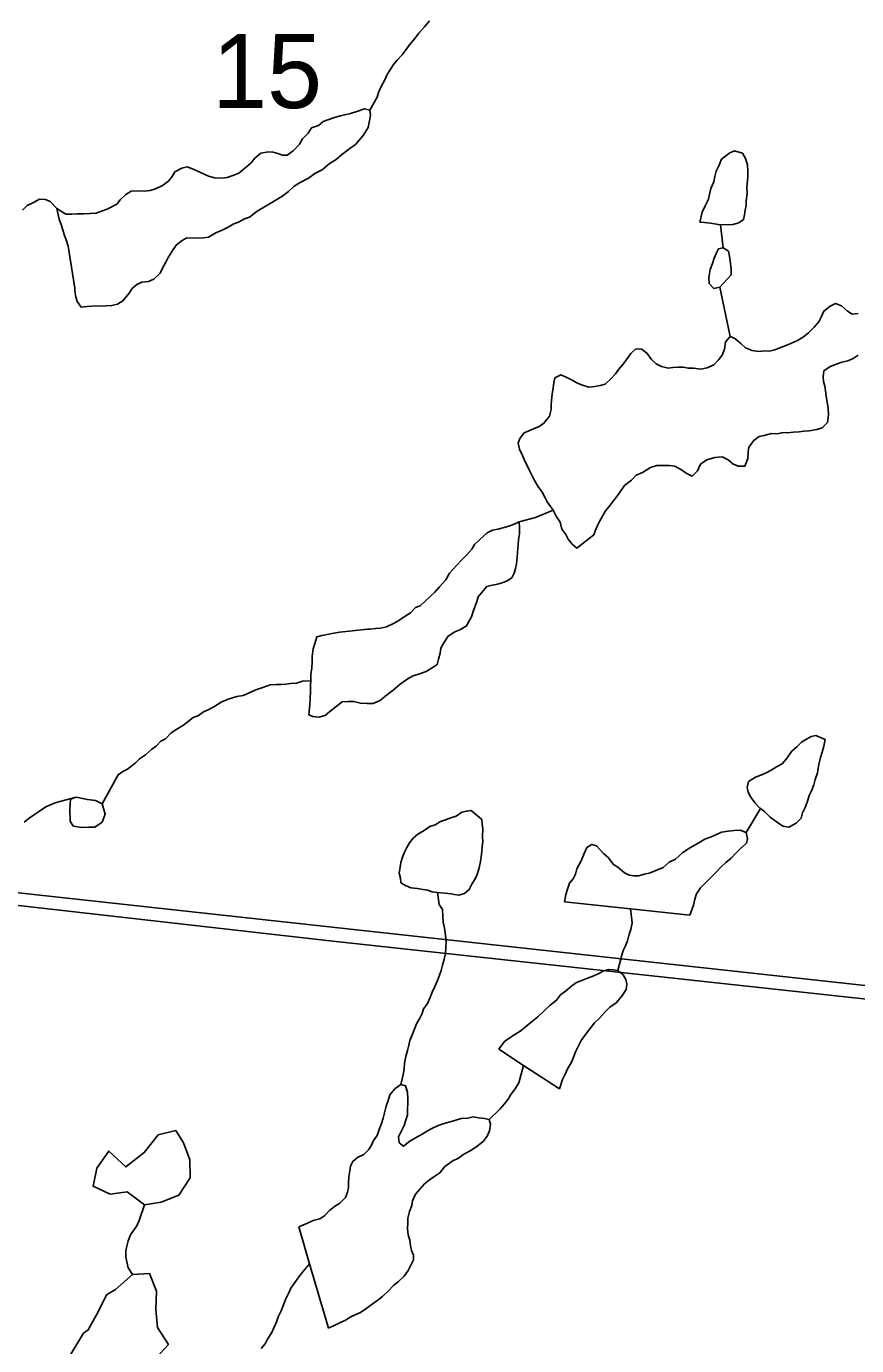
# Model space of a CAD drawing. Extents: x 1310247 to 1664935, y 284496 to 704931.
# Drawn here: x 1503058 to 1505539, y 507787 to 511730 of the extents above; entities that cross this region are included whole.
import ezdxf

# ---------------------------------------------------------------- set-up
doc = ezdxf.new("R2010")
doc.units = 0
for name, color, linetype in [('GM_X_County', 7, 'Continuous'), ('GM_X_County_Subdivision_Text', 7, 'Continuous'), ('GM_X_Minor_River', 7, 'Continuous'), ('GM_X_Minor_River_Text', 7, 'Continuous'), ('GM_X_US_Location', 7, 'Continuous')]:
    doc.layers.add(name, color=color, linetype=linetype)

msp = doc.modelspace()

# ---------------------------------------------------------------- linework, layer by layer
at = {"layer": 'GM_X_County'}
for points in [[(1501457.6, 514459.3), (1506637.6, 513990.6), (1506128.6, 508801.3), (1500914.6, 509372.6)], [(1500914.6, 509372.6), (1506128.6, 508801.3), (1505662.2, 503437.3), (1500316.1, 503893.5)]]:
    msp.add_lwpolyline(points, close=True, dxfattribs=at)
at = {"layer": 'GM_X_County_Subdivision_Text'}
msp.add_lwpolyline([(1502061.4, 509213.1), (1502095.3, 509209.3), (1503964.4, 508997.2), (1506100.4, 508764.4)], dxfattribs=at)
at = {"layer": 'GM_X_Minor_River'}
for points in [[(1503295.9, 510894.9), (1503314, 510896.3), (1503330.2, 510899.8), (1503346.6, 510909.4), (1503365.5, 510932.8), (1503373.9, 510946.6), (1503388.4, 510958.2), (1503402.7, 510965.7), (1503422.9, 510967.1), (1503439.2, 510974.6), (1503457.8, 510992.1), (1503464.4, 511007.9), (1503475, 511025.6), (1503481.5, 511039.4), (1503496.4, 511063), (1503506.9, 511076.7), (1503523.4, 511090.2), (1503537.7, 511097.8), (1503565.8, 511096.9), (1503587.9, 511098.2), (1503602.1, 511099.8), (1503624.6, 511113.1), (1503642.9, 511120.6), (1503661.3, 511130), (1503677.7, 511139.6), (1503692, 511145.1), (1503710.4, 511154.6), (1503724.6, 511160.2), (1503747.3, 511177.5), (1503769.8, 511190.8), (1503786.2, 511200.3), (1503821.1, 511221.3), (1503841.7, 511236.7), (1503858.2, 511252.2), (1503876.7, 511263.6), (1503901.3, 511276.9), (1503919.8, 511290.4), (1503942.3, 511301.7), (1503962.9, 511319.1), (1503983.5, 511332.5), (1504000, 511346), (1504024.7, 511365.3), (1504041.2, 511376.8), (1504064.2, 511404.1), (1504079, 511427.7), (1504083.7, 511447.6), (1504086.3, 511465.5), (1504084.8, 511479.6), (1504068.9, 511484.1), (1504048.5, 511476.7), (1504026.2, 511469.4), (1504010, 511465.9), (1503995.8, 511462.3), (1503975.5, 511456.9), (1503945, 511445.9), (1503930.6, 511434.3), (1503910.2, 511426.9), (1503899.7, 511411.2), (1503883, 511393.7), (1503874.5, 511377.9), (1503855.7, 511358.5), (1503837.2, 511345), (1503823.2, 511345.4), (1503809.2, 511349.9), (1503795.3, 511354.3), (1503781.3, 511354.8), (1503759.1, 511351.4), (1503740.5, 511336), (1503730, 511322.3), (1503715.5, 511310.7), (1503692.8, 511291.4), (1503678.5, 511285.8), (1503658.2, 511278.4), (1503642.1, 511276.9), (1503620, 511277.6), (1503602, 511282.1), (1503574.3, 511295), (1503556.5, 511303.6), (1503538.7, 511310.1), (1503522.5, 511306.6), (1503502, 511295.2), (1503493.5, 511281.5), (1503483, 511267.8), (1503464.5, 511254.3), (1503444.1, 511245), (1503427.8, 511239.5), (1503409.7, 511238), (1503391.6, 511238.6), (1503371.5, 511237.2), (1503355.1, 511227.7), (1503338.5, 511212.1), (1503328, 511198.5), (1503299.4, 511183.3), (1503283.1, 511177.8), (1503266.9, 511172.3), (1503248.7, 511170.8), (1503230.6, 511169.4), (1503208.5, 511170.1), (1503194.4, 511168.5), (1503176.3, 511169.1), (1503148.8, 511186)], [(1505131.9, 511137.4), (1505168.6, 511137.6), (1505186.8, 511143), (1505201.2, 511152.6), (1505203.7, 511166.6), (1505206.1, 511180.5), (1505208.6, 511194.5), (1505209.1, 511208.5), (1505211.8, 511230.4), (1505210.4, 511248.5), (1505213.5, 511280.5), (1505214.1, 511298.5), (1505212.6, 511316.5), (1505207.2, 511334.8), (1505197.7, 511351.1), (1505173.8, 511357.8), (1505159.6, 511352.2), (1505134.8, 511333), (1505128.2, 511315.1), (1505119.6, 511297.4), (1505115, 511281.5), (1505112.5, 511265.6), (1505103.8, 511245.8), (1505099.2, 511227.9), (1505096.7, 511214), (1505086, 511194.2), (1505077.3, 511174.5), (1505070.4, 511144.6)], [(1503148.8, 511186), (1503152.3, 511171.8), (1503155.7, 511153.7), (1503163.2, 511135.4), (1503166.7, 511121.3), (1503172.2, 511105.1), (1503177.7, 511088.9), (1503183.2, 511072.7), (1503202.5, 510948.1)], [(1505070.4, 511144.6), (1505084.4, 511144.2), (1505102.4, 511141.6), (1505120.4, 511139.1), (1505131.9, 511137.4)], [(1505130.2, 510950.5), (1505112, 510947), (1505098.4, 510961.4), (1505097, 510979.5), (1505101.8, 511003.4), (1505108.4, 511021.2), (1505113, 511037.1), (1505119.5, 511051), (1505126, 511064.8), (1505140.1, 511068.3), (1505155.9, 511057.8), (1505159.4, 511043.7), (1505161, 511029.6), (1505164.1, 511003.5), (1505163.6, 510987.5), (1505130.2, 510950.5)], [(1505119.5, 511051), (1505113, 511037.1), (1505108.4, 511021.2), (1505101.8, 511003.4), (1505097, 510979.5), (1505098.4, 510961.4), (1505112, 510947), (1505130.2, 510950.5)], [(1505130.2, 510950.5), (1505163.6, 510987.5), (1505164.1, 511003.5), (1505161, 511029.6), (1505159.4, 511043.7), (1505155.9, 511057.8), (1505140.1, 511068.3), (1505126, 511064.8), (1505119.5, 511051)], [(1503202.5, 510948.1), (1503203, 510941.8), (1503204.5, 510925.8), (1503209.9, 510907.6), (1503221.4, 510891.2), (1503239.6, 510892.6), (1503253.7, 510894.2), (1503295.9, 510894.9)], [(1505543.5, 510871.6), (1505525.4, 510870.1), (1505511.6, 510878.6), (1505494.1, 510895.1), (1505476.2, 510901.7), (1505459.9, 510894.2), (1505441.3, 510878.7), (1505432.7, 510861), (1505426.2, 510847.1), (1505411.6, 510831.6), (1505395, 510814), (1505380.5, 510802.5), (1505362, 510791), (1505335.6, 510779.8), (1505317.2, 510772.4), (1505294.8, 510763), (1505278.6, 510759.5), (1505264.6, 510760), (1505246.4, 510758.5), (1505226.4, 510761.1), (1505206.6, 510769.8), (1505193, 510782.2), (1505175.4, 510796.8), (1505161.5, 510803.2), (1505146.9, 510787.6)], [(1505146.9, 510787.6), (1505144.2, 510765.7), (1505137.6, 510747.9), (1505127.1, 510734.2), (1505112.5, 510718.6), (1505092.1, 510709.2), (1505073.9, 510705.8), (1505051.9, 510708.4), (1505035.8, 510708.9), (1505021.9, 510711.4), (1505005.8, 510711.9), (1504989.7, 510710.4), (1504975.6, 510708.8), (1504955.6, 510713.4), (1504939.8, 510721.9), (1504926.2, 510734.4), (1504912.7, 510752.8), (1504897, 510765.3), (1504879, 510765.9), (1504864.5, 510752.3), (1504854, 510738.6), (1504841.3, 510721), (1504828.8, 510705.3), (1504818.3, 510691.6), (1504805.8, 510678), (1504787.1, 510660.5), (1504772.9, 510657), (1504756.7, 510653.4), (1504738.6, 510652), (1504716.7, 510658.7), (1504702.8, 510665.1), (1504687.1, 510673.6), (1504671.3, 510682.1), (1504655.4, 510688.6), (1504637, 510679.2), (1504634.5, 510665.2), (1504632, 510649.3), (1504629.4, 510631.3), (1504626.8, 510613.4), (1504626.3, 510599.4), (1504625.9, 510585.3), (1504621.2, 510565.5), (1504604.4, 510543.9), (1504590, 510534.4), (1504573.7, 510526.9), (1504559.5, 510521.3), (1504545.2, 510515.7), (1504532.6, 510498.1), (1504528.1, 510484.2), (1504531.5, 510466), (1504540.9, 510447.7), (1504546.5, 510433.5), (1504559.7, 510407.1), (1504567.2, 510390.8), (1504576.6, 510372.5), (1504586.2, 510356.2), (1504599.6, 510337.7), (1504607.2, 510323.5), (1504614.7, 510309.2), (1504632, 510284.6), (1504641.5, 510266.3), (1504652.9, 510247.9), (1504658.3, 510227.7), (1504669.8, 510211.3), (1504677.3, 510197.1), (1504688.9, 510182.7), (1504702.6, 510170.3)], [(1505449.7, 510612.1), (1505443.9, 510654.3), (1505440.4, 510668.4), (1505438.8, 510682.5), (1505441.4, 510700.4), (1505460, 510713.9), (1505476.2, 510719.4), (1505494.5, 510726.8), (1505512.7, 510730.3), (1505529.1, 510737.8), (1505543.4, 510747.3)], [(1504702.6, 510170.3), (1504754.1, 510210.7), (1504758.6, 510224.6), (1504765.1, 510238.4), (1504771.6, 510252.3), (1504788.6, 510281.8), (1504799.1, 510295.5), (1504811.7, 510311.1), (1504822.2, 510324.8), (1504832.7, 510338.5), (1504845.4, 510358.2), (1504866, 510373.6), (1504880.6, 510389.1), (1504898.9, 510396.6), (1504923.5, 510411.9), (1504941.8, 510417.3), (1504980, 510418.1), (1504996, 510415.6), (1505015.8, 510405), (1505029.5, 510394.6), (1505047.3, 510386), (1505063.9, 510401.5), (1505072.6, 510421.3), (1505091.1, 510434.7), (1505115.4, 510442), (1505137.6, 510443.3), (1505155.4, 510434.8), (1505169, 510422.3), (1505184.9, 510415.8), (1505205, 510415.2), (1505213.8, 510439), (1505214.4, 510459), (1505216.9, 510472.9), (1505231.6, 510492.5), (1505248.1, 510504), (1505262.3, 510507.6), (1505284.5, 510512.9), (1505302.6, 510512.4), (1505318.8, 510515.9), (1505332.8, 510515.4), (1505349, 510516.9), (1505367.1, 510518.4), (1505381.2, 510520), (1505397.3, 510521.5), (1505419.6, 510524.8), (1505435.8, 510530.3), (1505452.4, 510545.8), (1505455.2, 510569.8), (1505453.8, 510587.8), (1505452.3, 510601.9), (1505449.7, 510612.1)], [(1503902.5, 509672), (1503914.4, 509667.7), (1503932.4, 509665.1), (1503950.7, 509670.5), (1503965.1, 509682.1), (1503983.7, 509697.6), (1504002.2, 509711), (1504020.4, 509712.5), (1504036.4, 509712), (1504056.4, 509707.3), (1504076.4, 509706.7), (1504094.5, 509706.2), (1504114.9, 509715.6), (1504129.3, 509727.1), (1504154.1, 509746.4), (1504174.8, 509763.8), (1504199.4, 509781.1), (1504213.8, 509788.6), (1504236.1, 509796), (1504252.4, 509801.5), (1504270.8, 509812.9), (1504285.2, 509822.5), (1504289.7, 509838.4), (1504294.4, 509856.3), (1504296.9, 509872.2), (1504305.4, 509888), (1504318.2, 509907.6), (1504338.7, 509921), (1504352.9, 509926.6), (1504373.4, 509938), (1504379.9, 509951.8), (1504388.4, 509965.6), (1504392.9, 509981.5), (1504404, 510011.2), (1504408.4, 510025.1), (1504423.1, 510042.6), (1504433.6, 510056.3), (1504449.8, 510059.8), (1504466, 510063.4), (1504480.1, 510066.9), (1504494.4, 510072.5), (1504508.8, 510082.1), (1504515.3, 510095.9), (1504519.7, 510109.8), (1504522.2, 510123.7), (1504524.9, 510143.7), (1504525.3, 510157.7), (1504528.1, 510181.6), (1504528.6, 510195.7), (1504531.2, 510213.6), (1504531.7, 510229.6), (1504530.4, 510249.7), (1504516.1, 510242.1), (1504499.8, 510236.6), (1504481.6, 510231.2), (1504467.4, 510227.6), (1504451.2, 510224.1), (1504434.9, 510216.6), (1504412, 510195.2), (1504397.5, 510181.7), (1504389, 510167.9), (1504374.4, 510150.3), (1504359.9, 510136.8), (1504343.2, 510119.2), (1504322.4, 510095.8), (1504311.7, 510076.1), (1504292.9, 510054.7), (1504278.3, 510039.1), (1504263.8, 510025.5), (1504249.3, 510011.9), (1504234.8, 509998.4), (1504220.5, 509992.8), (1504205.9, 509977.2), (1504189.5, 509967.7), (1504171, 509954.3), (1504156.7, 509946.7), (1504134.2, 509935.4), (1504116, 509931.9), (1504101.9, 509930.3), (1504085.8, 509928.8), (1504077.8, 509928.4)], [(1504077.8, 509928.4), (1503995.1, 509919.6), (1503976.9, 509916.2), (1503956.7, 509912.8), (1503940.5, 509909.3), (1503926.3, 509905.7), (1503919.6, 509885.9), (1503915, 509870), (1503912.3, 509848), (1503911.8, 509832), (1503911.1, 509812), (1503908.5, 509794.1), (1503907.9, 509774), (1503907.4, 509760), (1503906.8, 509742), (1503906.1, 509720), (1503905.5, 509702), (1503902.5, 509672)], [(1505445.2, 509598.3), (1505417.5, 509611.2), (1505403.3, 509607.7), (1505389, 509600.1), (1505374.6, 509590.5), (1505360.1, 509576.9), (1505345.6, 509563.4), (1505328.7, 509539.8), (1505316.2, 509526.2), (1505299.8, 509516.7), (1505283.5, 509507.2), (1505267.1, 509497.7), (1505252.8, 509492.1), (1505236.6, 509486.6), (1505216, 509473.2), (1505211.4, 509455.3), (1505215, 509441.2), (1505222.5, 509426.9), (1505236, 509408.5), (1505249.6, 509394), (1505251.3, 509392.7)], [(1505251.3, 509392.7), (1505263.3, 509383.6), (1505280.8, 509367), (1505302.4, 509350.3), (1505318.1, 509339.8), (1505336.1, 509337.2), (1505358.6, 509348.6), (1505373.2, 509364.1), (1505377.7, 509380), (1505386.3, 509397.8), (1505393, 509417.6), (1505397.5, 509431.5), (1505404, 509445.3), (1505410.6, 509463.2), (1505415.1, 509479.1), (1505421.8, 509498.9), (1505424.3, 509512.8), (1505426.8, 509528.8), (1505431.4, 509544.7), (1505435.9, 509560.6), (1505440.5, 509578.5), (1505445.2, 509598.3)], [(1504387.3, 509386.6), (1504373.2, 509385), (1504359, 509381.5), (1504342.6, 509369.9), (1504326.3, 509364.4), (1504310.1, 509358.9), (1504295.8, 509353.3), (1504279.4, 509343.8), (1504263.2, 509338.3), (1504246.7, 509326.8), (1504228.3, 509315.4), (1504213.8, 509303.8), (1504203.3, 509290.1), (1504194.8, 509276.3), (1504188.3, 509262.5), (1504181.8, 509246.7), (1504177.2, 509230.8), (1504174.8, 509216.8), (1504172.2, 509198.9), (1504175.7, 509184.8), (1504177.3, 509170.7), (1504191.1, 509162.2), (1504206.9, 509155.7), (1504226.9, 509153.1), (1504242.9, 509150.6), (1504256.9, 509148.2), (1504270.8, 509143.7), (1504286.7, 509141.3)], [(1504286.7, 509141.3), (1504328.4, 509137.5), (1504336.9, 509135.7), (1504350.8, 509133.3), (1504367.1, 509138.8), (1504381.5, 509150.3), (1504390.2, 509168.1), (1504398.7, 509181.9), (1504405.1, 509195.7), (1504409.7, 509211.6), (1504414.3, 509229.5), (1504416.9, 509247.4), (1504419.5, 509265.4), (1504420, 509279.4), (1504422.4, 509293.3), (1504420.9, 509307.4), (1504421.7, 509331.4), (1504420.1, 509345.5), (1504418.6, 509359.6), (1504387.3, 509386.6)], [(1505040.1, 509073.9), (1505051.1, 509103.6), (1505055.7, 509121.5), (1505060.3, 509137.4), (1505072.9, 509155), (1505095.8, 509178.4), (1505120.7, 509203.6), (1505133.2, 509217.3), (1505147.7, 509230.9), (1505164.3, 509244.4), (1505176.8, 509258), (1505191.3, 509271.6), (1505209.9, 509289), (1505212.4, 509303), (1505209, 509321.1), (1505191.1, 509327.7), (1505173, 509326.3), (1505154.9, 509324.8), (1505134.7, 509321.4), (1505118.3, 509313.9), (1505104.1, 509308.3), (1505085.8, 509300.9), (1505067.3, 509289.5), (1505042.7, 509276.2), (1505020.1, 509260.8), (1504997.4, 509241.5), (1504979, 509232.1), (1504960.4, 509216.6), (1504944.1, 509209.1), (1504921.7, 509199.8), (1504905.5, 509196.3), (1504887.2, 509190.8), (1504873.2, 509191.3), (1504859.2, 509193.7), (1504845.3, 509200.1), (1504825.8, 509216.8), (1504812, 509225.2), (1504796.6, 509245.7), (1504783, 509258.2), (1504761.6, 509280.9), (1504747.7, 509285.3), (1504733.3, 509275.7), (1504724.7, 509258), (1504715.9, 509236.2), (1504703.1, 509212.5), (1504698.5, 509196.6), (1504692, 509182.8), (1504681.5, 509169.1), (1504674.9, 509151.3), (1504670.4, 509135.4), (1504665.6, 509113.5)], [(1504665.6, 509113.5), (1504863.3, 509092.6)], [(1504863.3, 509092.6), (1505040.1, 509073.9)], [(1504651.2, 508555), (1504660.2, 508582.8), (1504668.8, 508600.5), (1504675.3, 508614.3), (1504685.9, 508632), (1504692.4, 508645.9), (1504699.1, 508665.7), (1504707.7, 508683.5), (1504716.3, 508699.2), (1504728.9, 508716.9), (1504741.5, 508734.5), (1504756.2, 508752.1), (1504770.7, 508765.7), (1504787.4, 508785.2), (1504801.9, 508798.8), (1504820.5, 508812.2), (1504837.2, 508831.7), (1504849.9, 508851.4), (1504852.4, 508867.3), (1504848.9, 508881.5), (1504841.3, 508895.7), (1504825.6, 508908.2), (1504811.6, 508910.7), (1504797.6, 508911.1), (1504783.4, 508907.5), (1504767, 508898), (1504748.7, 508890.6), (1504734.4, 508885), (1504720.2, 508879.4), (1504701.9, 508872), (1504687.5, 508862.4), (1504668.9, 508847), (1504654.4, 508835.4), (1504641.9, 508819.7), (1504623.3, 508804.3), (1504606.7, 508788.8), (1504586, 508769.4), (1504571.5, 508757.8), (1504555, 508744.3), (1504536.4, 508728.8), (1504517.9, 508717.4), (1504503.6, 508707.8), (1504487.1, 508696.3), (1504470.2, 508672.8)], [(1504470.2, 508672.8), (1504543.9, 508624.8)], [(1504543.9, 508624.8), (1504651.2, 508555)], [(1503960.5, 507839), (1504011.5, 507863.5), (1504027.9, 507873), (1504042.2, 507880.6), (1504056.5, 507886.1), (1504072.9, 507897.6), (1504091.4, 507911.1), (1504107.9, 507922.6), (1504122.3, 507934.2), (1504138.9, 507949.7), (1504155.6, 507967.2), (1504170, 507978.8), (1504186.6, 507994.3), (1504199.3, 508012), (1504205.7, 508025.8), (1504214.4, 508043.5), (1504214.8, 508057.5), (1504209.3, 508071.7), (1504205.7, 508085.9), (1504204.2, 508102), (1504198.7, 508118.1), (1504197.3, 508136.2), (1504197.9, 508154.2), (1504198.4, 508168.2), (1504203.1, 508188.1), (1504209.7, 508206), (1504212.1, 508219.9), (1504220.8, 508239.7), (1504233.4, 508255.3), (1504248, 508270.9), (1504262.4, 508282.5), (1504278.9, 508294), (1504293.3, 508303.6), (1504307.9, 508321.1), (1504330.6, 508338.5), (1504349, 508347.9), (1504365.5, 508359.4), (1504383.8, 508368.9), (1504404.4, 508382.3), (1504425.1, 508399.7), (1504435.6, 508415.4), (1504442.1, 508429.2), (1504444.8, 508449.2), (1504441.2, 508463.3), (1504427.2, 508465.7), (1504409.2, 508468.3), (1504393.2, 508470.8), (1504377.1, 508467.3), (1504356.9, 508465.9), (1504338.7, 508460.5), (1504320.4, 508455), (1504306.2, 508451.4), (1504292, 508445.9), (1504273.6, 508438.4), (1504257.2, 508428.9), (1504240.9, 508419.4), (1504220.4, 508408), (1504204, 508398.5), (1504185.4, 508383), (1504171.7, 508393.5), (1504170.3, 508411.5), (1504176.7, 508425.4), (1504187.4, 508445.1), (1504192, 508461), (1504196.5, 508476.9), (1504197.1, 508494.9), (1504197.7, 508510.9), (1504198.1, 508524.9), (1504196.8, 508545), (1504191.3, 508563.2), (1504177.4, 508567.6), (1504158.9, 508554.2), (1504144.3, 508536.6), (1504139.8, 508522.7), (1504133.1, 508502.9), (1504128.4, 508483), (1504123.9, 508467.1), (1504119.3, 508451.2), (1504112.7, 508433.4), (1504106.1, 508415.5), (1504095.5, 508399.8), (1504089, 508386), (1504080.6, 508372.2), (1504066, 508358.7), (1504047.6, 508349.2), (1504033.2, 508337.6), (1504026.7, 508323.8), (1504024.2, 508309.9), (1504021.6, 508291.9), (1504021, 508273.9), (1504020.6, 508259.9), (1504018.1, 508246), (1504011.6, 508230.1), (1503994.9, 508212.6), (1503978.5, 508203.1), (1503964.1, 508191.5), (1503949.5, 508175.9), (1503935.1, 508166.4), (1503914.8, 508161), (1503898.5, 508153.5), (1503872, 508142.3)], [(1503504.5, 508430), (1503452, 508417.2), (1503410.5, 508364), (1503355.2, 508321.2), (1503304.1, 508368.6), (1503268.7, 508317.3), (1503257.3, 508263.3), (1503309, 508240), (1503359.4, 508246.8), (1503410.7, 508207.5), (1503461.1, 508216.3)], [(1503461.1, 508216.3), (1503513.9, 508237.1), (1503547.3, 508288.5), (1503546.6, 508342.7), (1503527.8, 508393.3), (1503504.5, 508430)], [(1503872, 508142.3), (1503904.2, 508032)], [(1503228.5, 507824.5), (1503190.8, 507761.2), (1503213.6, 507708.4), (1503269.5, 507693), (1503324.2, 507711.8), (1503376.7, 507722.6), (1503433.3, 507737.2), (1503482.8, 507790.2), (1503449.9, 507841.2), (1503445.2, 507895.5), (1503446.6, 507949.7), (1503425.7, 508002.4), (1503375.4, 507999.6), (1503324.1, 507954.6), (1503297.6, 507939.2)], [(1503904.2, 508032), (1503960.5, 507839)], [(1503297.6, 507939.2), (1503272.2, 507887.7), (1503242.8, 507834.2), (1503228.5, 507824.5)]]:
    msp.add_lwpolyline(points, dxfattribs=at)
at = {"layer": 'GM_X_Minor_River_Text'}
for points in [[(1504084.8, 511479.6), (1504106.2, 511519), (1504110.7, 511532.9), (1504119.3, 511552.7), (1504127.9, 511568.4), (1504136.5, 511586.2), (1504145, 511600), (1504155.6, 511615.7), (1504166.1, 511629.4), (1504180.7, 511645), (1504193.2, 511660.6), (1504201.7, 511674.4), (1504218.4, 511693.9), (1504231, 511709.5), (1504247.7, 511729), (1504262.4, 511746.6)], [(1503046.1, 511181.1), (1503060.7, 511194.7), (1503079.1, 511204.1), (1503097.5, 511213.6), (1503115.5, 511213), (1503129.4, 511206.6), (1503148.8, 511186)], [(1505140.1, 511068.3), (1505131.9, 511137.4)], [(1505161.5, 510803.2), (1505130.2, 510950.5)], [(1504530.4, 510249.7), (1504579, 510262.2), (1504632, 510284.6)], [(1503395.8, 509541.4), (1503414.3, 509552.9), (1503433, 509570.3), (1503447.3, 509579.9), (1503459.8, 509593.5), (1503474.2, 509601.1), (1503490.8, 509618.6), (1503507.3, 509630.1), (1503527.7, 509641.5), (1503542.2, 509653.1), (1503556.6, 509664.7), (1503572.9, 509670.2), (1503587.3, 509681.8), (1503601.6, 509687.3), (1503618, 509696.8), (1503640.5, 509710.2), (1503660.9, 509719.6), (1503687.3, 509726.8), (1503705.5, 509730.2), (1503721.8, 509737.7), (1503744.2, 509747), (1503764.5, 509754.4), (1503786.9, 509761.8), (1503805, 509763.2), (1503819.1, 509762.8), (1503833.2, 509764.3), (1503847.3, 509765.9), (1503865.4, 509767.3), (1503883.7, 509772.8), (1503907.9, 509774)], [(1503284.4, 509406.1), (1503332, 509493.3), (1503346.3, 509502.9), (1503360.7, 509510.5), (1503383.3, 509527.8), (1503395.8, 509541.4)], [(1503052, 509351.7), (1503066.5, 509363.3), (1503082.9, 509374.8), (1503097.3, 509384.3), (1503115.8, 509397.8), (1503130.1, 509403.4), (1503144.3, 509409), (1503162.6, 509414.4), (1503206.5, 509426)], [(1503198.4, 509340), (1503188.7, 509354.2), (1503187.6, 509390.4), (1503190.3, 509420.4), (1503206.5, 509426)], [(1503206.5, 509426), (1503240.5, 509419.2), (1503264.5, 509416.6), (1503284.4, 509406.1), (1503293.7, 509375.8), (1503285.1, 509351.9), (1503262.6, 509336.4), (1503244.5, 509336.8), (1503224.4, 509335.3), (1503198.4, 509340)], [(1505209, 509321.1), (1505251.3, 509392.7)], [(1504177.4, 508567.6), (1504184.6, 508601.4), (1504187, 508615.4), (1504187.6, 508631.4), (1504192.2, 508651.3), (1504196.9, 508669.2), (1504201.4, 508685.1), (1504203.9, 508699), (1504210.4, 508712.8), (1504217, 508730.7), (1504223.6, 508748.5), (1504234.2, 508766.2), (1504240.7, 508780), (1504245.2, 508793.9), (1504255.7, 508807.6), (1504264.4, 508827.4), (1504270.9, 508843.2), (1504279.6, 508863), (1504286.2, 508878.8), (1504292.7, 508894.6), (1504297.2, 508908.5), (1504301.7, 508924.4), (1504306.3, 508942.3), (1504310.9, 508958.2), (1504311.5, 508976.2), (1504312.1, 508996.2), (1504310.7, 509014.3), (1504307.4, 509034.4), (1504304, 509052.6), (1504302.6, 509070.6), (1504301.2, 509090.7), (1504291.7, 509105.2), (1504286.7, 509141.3)], [(1504825.6, 508908.2), (1504837.2, 508954), (1504841.7, 508967.8), (1504848.2, 508981.7), (1504854.7, 508997.5), (1504859.4, 509017.4), (1504863.9, 509031.3), (1504868.5, 509051.2), (1504863.3, 509092.6)], [(1504441.2, 508463.3), (1504472.4, 508494.4), (1504487, 508510), (1504497.5, 508523.7), (1504506, 508537.4), (1504518.6, 508555.1), (1504529.2, 508572.8), (1504543.9, 508624.8)], [(1503375.4, 507999.6), (1503362.1, 508020), (1503358.6, 508038.1), (1503355.1, 508052.3), (1503355.7, 508070.3), (1503358.1, 508084.2), (1503362.7, 508100.1), (1503369.3, 508118), (1503377.8, 508131.7), (1503388.3, 508145.4), (1503394.9, 508161.2), (1503410.7, 508207.5)], [(1503759.6, 507779.1), (1503772.1, 507792.7), (1503778.5, 507806.6), (1503791.3, 507826.2), (1503797.7, 507840), (1503804.3, 507855.8), (1503810.9, 507873.7), (1503819.5, 507891.4), (1503826.2, 507909.3), (1503832.7, 507925.1), (1503841.3, 507942.9), (1503847.9, 507958.7), (1503858.4, 507972.4), (1503866.9, 507986.1), (1503879.4, 508001.8), (1503904.2, 508032)]]:
    msp.add_lwpolyline(points, dxfattribs=at)

# ---------------------------------------------------------------- texts
at = {"layer": 'GM_X_US_Location'}
msp.add_text('15', height=221, rotation=0, dxfattribs=at).set_placement((1503613, 511486))

doc.saveas('drawing.dxf')
